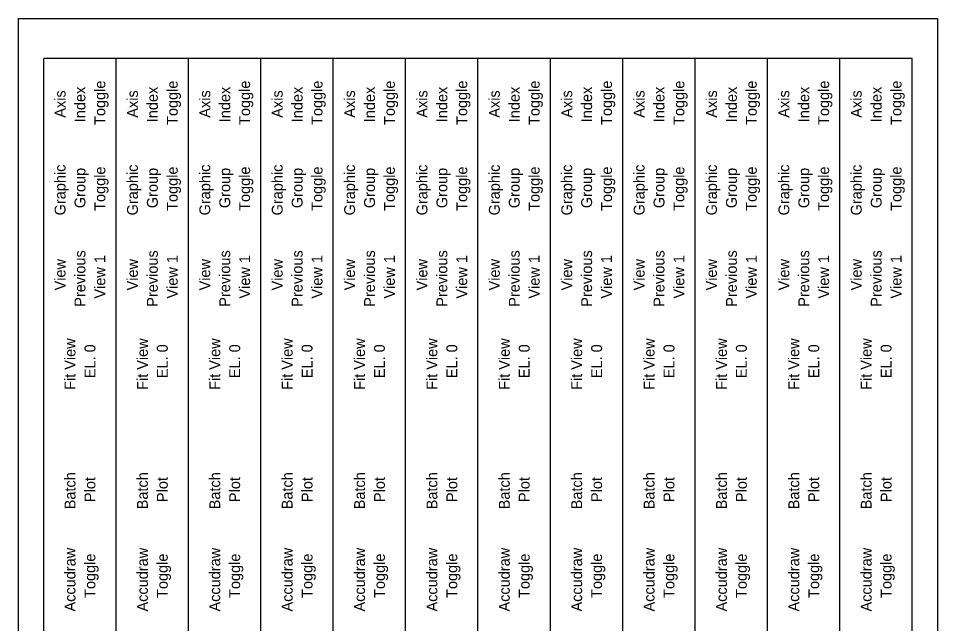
# Model space of a CAD drawing. Extents: x 605371.3 to 605398.1, y 420183.2 to 420214.1.
# Drawn here: x 605390.9472 to 605391.1504, y 420197.4785 to 420197.6124 of the extents above; entities that cross this region are included whole.
import ezdxf

# ---------------------------------------------------------------- set-up
doc = ezdxf.new("R2010")
doc.units = 0
doc.layers.add('Level 60', color=7, linetype='Continuous')
doc.layers.add('Notes', color=7, linetype='Continuous')

msp = doc.modelspace()

# ---------------------------------------------------------------- linework, layer by layer
at = {"layer": 'Level 60'}
msp.add_lwpolyline([(605391.15038, 420197.34467), (605390.94718, 420197.34467), (605390.94718, 420197.61237), (605391.15038, 420197.61237)], close=True, dxfattribs=at)
msp.add_lwpolyline([(605391.15038, 420197.34467), (605390.94718, 420197.34467), (605390.94718, 420197.61237), (605391.15038, 420197.61237)], close=True, dxfattribs=at)
at = {"layer": 'Notes'}
for p, q in [((605390.95278, 420197.35352), (605390.95278, 420197.60352)), ((605390.96878, 420197.60352), (605390.95278, 420197.60352)), ((605390.95278, 420197.35352), (605390.95278, 420197.60352)), ((605390.96878, 420197.60352), (605390.95278, 420197.60352)), ((605390.96878, 420197.35352), (605390.96878, 420197.60352)), ((605390.98478, 420197.60352), (605390.96878, 420197.60352)), ((605390.96878, 420197.35352), (605390.96878, 420197.60352)), ((605390.98478, 420197.60352), (605390.96878, 420197.60352)), ((605390.98478, 420197.35352), (605390.98478, 420197.60352)), ((605391.00078, 420197.60352), (605390.98478, 420197.60352)), ((605390.98478, 420197.35352), (605390.98478, 420197.60352)), ((605391.00078, 420197.60352), (605390.98478, 420197.60352)), ((605391.00078, 420197.35352), (605391.00078, 420197.60352)), ((605391.01678, 420197.60352), (605391.00078, 420197.60352)), ((605391.00078, 420197.35352), (605391.00078, 420197.60352)), ((605391.01678, 420197.60352), (605391.00078, 420197.60352)), ((605391.01678, 420197.35352), (605391.01678, 420197.60352)), ((605391.03278, 420197.60352), (605391.01678, 420197.60352)), ((605391.01678, 420197.35352), (605391.01678, 420197.60352)), ((605391.03278, 420197.60352), (605391.01678, 420197.60352)), ((605391.03278, 420197.35352), (605391.03278, 420197.60352)), ((605391.04878, 420197.60352), (605391.03278, 420197.60352)), ((605391.03278, 420197.35352), (605391.03278, 420197.60352)), ((605391.04878, 420197.60352), (605391.03278, 420197.60352)), ((605391.04878, 420197.35352), (605391.04878, 420197.60352)), ((605391.06478, 420197.60352), (605391.04878, 420197.60352)), ((605391.04878, 420197.35352), (605391.04878, 420197.60352)), ((605391.06478, 420197.60352), (605391.04878, 420197.60352)), ((605391.06478, 420197.35352), (605391.06478, 420197.60352)), ((605391.08078, 420197.60352), (605391.06478, 420197.60352)), ((605391.06478, 420197.35352), (605391.06478, 420197.60352)), ((605391.08078, 420197.60352), (605391.06478, 420197.60352)), ((605391.08078, 420197.35352), (605391.08078, 420197.60352)), ((605391.09678, 420197.60352), (605391.08078, 420197.60352)), ((605391.08078, 420197.35352), (605391.08078, 420197.60352)), ((605391.09678, 420197.60352), (605391.08078, 420197.60352)), ((605391.09678, 420197.35352), (605391.09678, 420197.60352)), ((605391.11278, 420197.60352), (605391.09678, 420197.60352)), ((605391.09678, 420197.35352), (605391.09678, 420197.60352)), ((605391.11278, 420197.60352), (605391.09678, 420197.60352)), ((605391.11278, 420197.35352), (605391.11278, 420197.60352)), ((605391.12878, 420197.60352), (605391.11278, 420197.60352)), ((605391.11278, 420197.35352), (605391.11278, 420197.60352)), ((605391.12878, 420197.60352), (605391.11278, 420197.60352)), ((605391.12878, 420197.35352), (605391.12878, 420197.60352)), ((605391.14478, 420197.60352), (605391.12878, 420197.60352)), ((605391.12878, 420197.35352), (605391.12878, 420197.60352)), ((605391.14478, 420197.60352), (605391.12878, 420197.60352)), ((605391.14478, 420197.35352), (605391.14478, 420197.60352)), ((605391.14478, 420197.35352), (605391.14478, 420197.60352))]:
    msp.add_line(p, q, dxfattribs=at)

# ---------------------------------------------------------------- texts
for s, p in [('Index', (605390.962, 420197.5894)), ('Index', (605390.962, 420197.5894)), ('Toggle', (605390.9664, 420197.5888)), ('Toggle', (605390.9664, 420197.5888)), ('Index', (605390.978, 420197.5894)), ('Index', (605390.978, 420197.5894)), ('Toggle', (605390.9824, 420197.5888)), ('Toggle', (605390.9824, 420197.5888)), ('Index', (605390.994, 420197.5894)), ('Index', (605390.994, 420197.5894)), ('Toggle', (605390.9984, 420197.5888)), ('Toggle', (605390.9984, 420197.5888)), ('Index', (605391.01, 420197.5894)), ('Index', (605391.01, 420197.5894)), ('Toggle', (605391.0144, 420197.5888)), ('Toggle', (605391.0144, 420197.5888)), ('Index', (605391.026, 420197.5894)), ('Index', (605391.026, 420197.5894)), ('Toggle', (605391.0304, 420197.5888)), ('Toggle', (605391.0304, 420197.5888)), ('Index', (605391.042, 420197.5894)), ('Index', (605391.042, 420197.5894)), ('Toggle', (605391.0464, 420197.5888)), ('Toggle', (605391.0464, 420197.5888)), ('Index', (605391.058, 420197.5894)), ('Index', (605391.058, 420197.5894)), ('Toggle', (605391.0624, 420197.5888)), ('Toggle', (605391.0624, 420197.5888)), ('Index', (605391.074, 420197.5894)), ('Index', (605391.074, 420197.5894)), ('Toggle', (605391.0784, 420197.5888)), ('Toggle', (605391.0784, 420197.5888)), ('Index', (605391.09, 420197.5894)), ('Index', (605391.09, 420197.5894)), ('Toggle', (605391.0944, 420197.5888)), ('Toggle', (605391.0944, 420197.5888)), ('Index', (605391.106, 420197.5894)), ('Index', (605391.106, 420197.5894)), ('Toggle', (605391.1104, 420197.5888)), ('Toggle', (605391.1104, 420197.5888)), ('Index', (605391.122, 420197.5894)), ('Index', (605391.122, 420197.5894)), ('Toggle', (605391.1264, 420197.5888)), ('Toggle', (605391.1264, 420197.5888)), ('Index', (605391.138, 420197.5894)), ('Index', (605391.138, 420197.5894)), ('Toggle', (605391.1424, 420197.5888)), ('Toggle', (605391.1424, 420197.5888)), ('Axis', (605390.9576, 420197.5904)), ('Axis', (605390.9576, 420197.5904)), ('Axis', (605390.9736, 420197.5904)), ('Axis', (605390.9736, 420197.5904)), ('Axis', (605390.9896, 420197.5904)), ('Axis', (605390.9896, 420197.5904)), ('Axis', (605391.0056, 420197.5904)), ('Axis', (605391.0056, 420197.5904)), ('Axis', (605391.0216, 420197.5904)), ('Axis', (605391.0216, 420197.5904)), ('Axis', (605391.0376, 420197.5904)), ('Axis', (605391.0376, 420197.5904)), ('Axis', (605391.0536, 420197.5904)), ('Axis', (605391.0536, 420197.5904)), ('Axis', (605391.0696, 420197.5904)), ('Axis', (605391.0696, 420197.5904)), ('Axis', (605391.0856, 420197.5904)), ('Axis', (605391.0856, 420197.5904)), ('Axis', (605391.1016, 420197.5904)), ('Axis', (605391.1016, 420197.5904)), ('Axis', (605391.1176, 420197.5904)), ('Axis', (605391.1176, 420197.5904)), ('Axis', (605391.1336, 420197.5904)), ('Axis', (605391.1336, 420197.5904)), ('Graphic', (605390.9576, 420197.5688)), ('Graphic', (605390.9576, 420197.5688)), ('Group', (605390.962, 420197.5704)), ('Group', (605390.962, 420197.5704)), ('Toggle', (605390.9664, 420197.5698)), ('Toggle', (605390.9664, 420197.5698)), ('Graphic', (605390.9736, 420197.5688)), ('Graphic', (605390.9736, 420197.5688)), ('Group', (605390.978, 420197.5704)), ('Group', (605390.978, 420197.5704)), ('Toggle', (605390.9824, 420197.5698)), ('Toggle', (605390.9824, 420197.5698)), ('Graphic', (605390.9896, 420197.5688)), ('Graphic', (605390.9896, 420197.5688)), ('Group', (605390.994, 420197.5704)), ('Group', (605390.994, 420197.5704)), ('Toggle', (605390.9984, 420197.5698)), ('Toggle', (605390.9984, 420197.5698)), ('Graphic', (605391.0056, 420197.5688)), ('Graphic', (605391.0056, 420197.5688)), ('Group', (605391.01, 420197.5704)), ('Group', (605391.01, 420197.5704)), ('Toggle', (605391.0144, 420197.5698)), ('Toggle', (605391.0144, 420197.5698)), ('Graphic', (605391.0216, 420197.5688)), ('Graphic', (605391.0216, 420197.5688)), ('Group', (605391.026, 420197.5704)), ('Group', (605391.026, 420197.5704)), ('Toggle', (605391.0304, 420197.5698)), ('Toggle', (605391.0304, 420197.5698)), ('Graphic', (605391.0376, 420197.5688)), ('Graphic', (605391.0376, 420197.5688)), ('Group', (605391.042, 420197.5704)), ('Group', (605391.042, 420197.5704)), ('Toggle', (605391.0464, 420197.5698)), ('Toggle', (605391.0464, 420197.5698)), ('Graphic', (605391.0536, 420197.5688)), ('Graphic', (605391.0536, 420197.5688)), ('Group', (605391.058, 420197.5704)), ('Group', (605391.058, 420197.5704)), ('Toggle', (605391.0624, 420197.5698)), ('Toggle', (605391.0624, 420197.5698)), ('Graphic', (605391.0696, 420197.5688)), ('Graphic', (605391.0696, 420197.5688)), ('Group', (605391.074, 420197.5704)), ('Group', (605391.074, 420197.5704)), ('Toggle', (605391.0784, 420197.5698)), ('Toggle', (605391.0784, 420197.5698)), ('Graphic', (605391.0856, 420197.5688)), ('Graphic', (605391.0856, 420197.5688)), ('Group', (605391.09, 420197.5704)), ('Group', (605391.09, 420197.5704)), ('Toggle', (605391.0944, 420197.5698)), ('Toggle', (605391.0944, 420197.5698)), ('Graphic', (605391.1016, 420197.5688)), ('Graphic', (605391.1016, 420197.5688)), ('Group', (605391.106, 420197.5704)), ('Group', (605391.106, 420197.5704)), ('Toggle', (605391.1104, 420197.5698)), ('Toggle', (605391.1104, 420197.5698)), ('Graphic', (605391.1176, 420197.5688)), ('Graphic', (605391.1176, 420197.5688)), ('Group', (605391.122, 420197.5704)), ('Group', (605391.122, 420197.5704)), ('Toggle', (605391.1264, 420197.5698)), ('Toggle', (605391.1264, 420197.5698)), ('Graphic', (605391.1336, 420197.5688)), ('Graphic', (605391.1336, 420197.5688)), ('Group', (605391.138, 420197.5704)), ('Group', (605391.138, 420197.5704)), ('Toggle', (605391.1424, 420197.5698)), ('Toggle', (605391.1424, 420197.5698)), ('Previous', (605390.962, 420197.5486)), ('Previous', (605390.962, 420197.5486)), ('Previous', (605390.978, 420197.5486)), ('Previous', (605390.978, 420197.5486)), ('Previous', (605390.994, 420197.5486)), ('Previous', (605390.994, 420197.5486)), ('Previous', (605391.01, 420197.5486)), ('Previous', (605391.01, 420197.5486)), ('Previous', (605391.026, 420197.5486)), ('Previous', (605391.026, 420197.5486)), ('Previous', (605391.042, 420197.5486)), ('Previous', (605391.042, 420197.5486)), ('Previous', (605391.058, 420197.5486)), ('Previous', (605391.058, 420197.5486)), ('Previous', (605391.074, 420197.5486)), ('Previous', (605391.074, 420197.5486)), ('Previous', (605391.09, 420197.5486)), ('Previous', (605391.09, 420197.5486)), ('Previous', (605391.106, 420197.5486)), ('Previous', (605391.106, 420197.5486)), ('Previous', (605391.122, 420197.5486)), ('Previous', (605391.122, 420197.5486)), ('Previous', (605391.138, 420197.5486)), ('Previous', (605391.138, 420197.5486)), ('View', (605390.9576, 420197.5522)), ('View', (605390.9576, 420197.5522)), ('View 1', (605390.9664, 420197.5504)), ('View 1', (605390.9664, 420197.5504)), ('View', (605390.9736, 420197.5522)), ('View', (605390.9736, 420197.5522)), ('View 1', (605390.9824, 420197.5504)), ('View 1', (605390.9824, 420197.5504)), ('View', (605390.9896, 420197.5522)), ('View', (605390.9896, 420197.5522)), ('View 1', (605390.9984, 420197.5504)), ('View 1', (605390.9984, 420197.5504)), ('View', (605391.0056, 420197.5522)), ('View', (605391.0056, 420197.5522)), ('View 1', (605391.0144, 420197.5504)), ('View 1', (605391.0144, 420197.5504)), ('View', (605391.0216, 420197.5522)), ('View', (605391.0216, 420197.5522)), ('View 1', (605391.0304, 420197.5504)), ('View 1', (605391.0304, 420197.5504)), ('View', (605391.0376, 420197.5522)), ('View', (605391.0376, 420197.5522)), ('View 1', (605391.0464, 420197.5504)), ('View 1', (605391.0464, 420197.5504)), ('View', (605391.0536, 420197.5522)), ('View', (605391.0536, 420197.5522)), ('View 1', (605391.0624, 420197.5504)), ('View 1', (605391.0624, 420197.5504)), ('View', (605391.0696, 420197.5522)), ('View', (605391.0696, 420197.5522)), ('View 1', (605391.0784, 420197.5504)), ('View 1', (605391.0784, 420197.5504)), ('View', (605391.0856, 420197.5522)), ('View', (605391.0856, 420197.5522)), ('View 1', (605391.0944, 420197.5504)), ('View 1', (605391.0944, 420197.5504)), ('View', (605391.1016, 420197.5522)), ('View', (605391.1016, 420197.5522)), ('View 1', (605391.1104, 420197.5504)), ('View 1', (605391.1104, 420197.5504)), ('View', (605391.1176, 420197.5522)), ('View', (605391.1176, 420197.5522)), ('View 1', (605391.1264, 420197.5504)), ('View 1', (605391.1264, 420197.5504)), ('View', (605391.1336, 420197.5522)), ('View', (605391.1336, 420197.5522)), ('View 1', (605391.1424, 420197.5504)), ('View 1', (605391.1424, 420197.5504)), ('Fit View', (605390.9598, 420197.5302)), ('Fit View', (605390.9598, 420197.5302)), ('Fit View', (605390.9758, 420197.5302)), ('Fit View', (605390.9758, 420197.5302)), ('Fit View', (605390.9918, 420197.5302)), ('Fit View', (605390.9918, 420197.5302)), ('Fit View', (605391.0078, 420197.5302)), ('Fit View', (605391.0078, 420197.5302)), ('Fit View', (605391.0238, 420197.5302)), ('Fit View', (605391.0238, 420197.5302)), ('Fit View', (605391.0398, 420197.5302)), ('Fit View', (605391.0398, 420197.5302)), ('Fit View', (605391.0558, 420197.5302)), ('Fit View', (605391.0558, 420197.5302)), ('Fit View', (605391.0718, 420197.5302)), ('Fit View', (605391.0718, 420197.5302)), ('Fit View', (605391.0878, 420197.5302)), ('Fit View', (605391.0878, 420197.5302)), ('Fit View', (605391.1038, 420197.5302)), ('Fit View', (605391.1038, 420197.5302)), ('Fit View', (605391.1198, 420197.5302)), ('Fit View', (605391.1198, 420197.5302)), ('Fit View', (605391.1358, 420197.5302)), ('Fit View', (605391.1358, 420197.5302)), ('EL. 0', (605390.9642, 420197.5328)), ('EL. 0', (605390.9642, 420197.5328)), ('EL. 0', (605390.9802, 420197.5328)), ('EL. 0', (605390.9802, 420197.5328)), ('EL. 0', (605390.9962, 420197.5328)), ('EL. 0', (605390.9962, 420197.5328)), ('EL. 0', (605391.0122, 420197.5328)), ('EL. 0', (605391.0122, 420197.5328)), ('EL. 0', (605391.0282, 420197.5328)), ('EL. 0', (605391.0282, 420197.5328)), ('EL. 0', (605391.0442, 420197.5328)), ('EL. 0', (605391.0442, 420197.5328)), ('EL. 0', (605391.0602, 420197.5328)), ('EL. 0', (605391.0602, 420197.5328)), ('EL. 0', (605391.0762, 420197.5328)), ('EL. 0', (605391.0762, 420197.5328)), ('EL. 0', (605391.0922, 420197.5328)), ('EL. 0', (605391.0922, 420197.5328)), ('EL. 0', (605391.1082, 420197.5328)), ('EL. 0', (605391.1082, 420197.5328)), ('EL. 0', (605391.1242, 420197.5328)), ('EL. 0', (605391.1242, 420197.5328)), ('EL. 0', (605391.1402, 420197.5328)), ('EL. 0', (605391.1402, 420197.5328)), ('Batch', (605390.9598, 420197.5038)), ('Batch', (605390.9598, 420197.5038)), ('Plot', (605390.9642, 420197.5054)), ('Plot', (605390.9642, 420197.5054)), ('Batch', (605390.9758, 420197.5038)), ('Batch', (605390.9758, 420197.5038)), ('Plot', (605390.9802, 420197.5054)), ('Plot', (605390.9802, 420197.5054)), ('Batch', (605390.9918, 420197.5038)), ('Batch', (605390.9918, 420197.5038)), ('Plot', (605390.9962, 420197.5054)), ('Plot', (605390.9962, 420197.5054)), ('Batch', (605391.0078, 420197.5038)), ('Batch', (605391.0078, 420197.5038)), ('Plot', (605391.0122, 420197.5054)), ('Plot', (605391.0122, 420197.5054)), ('Batch', (605391.0238, 420197.5038)), ('Batch', (605391.0238, 420197.5038)), ('Plot', (605391.0282, 420197.5054)), ('Plot', (605391.0282, 420197.5054)), ('Batch', (605391.0398, 420197.5038)), ('Batch', (605391.0398, 420197.5038)), ('Plot', (605391.0442, 420197.5054)), ('Plot', (605391.0442, 420197.5054)), ('Batch', (605391.0558, 420197.5038)), ('Batch', (605391.0558, 420197.5038)), ('Plot', (605391.0602, 420197.5054)), ('Plot', (605391.0602, 420197.5054)), ('Batch', (605391.0718, 420197.5038)), ('Batch', (605391.0718, 420197.5038)), ('Plot', (605391.0762, 420197.5054)), ('Plot', (605391.0762, 420197.5054)), ('Batch', (605391.0878, 420197.5038)), ('Batch', (605391.0878, 420197.5038)), ('Plot', (605391.0922, 420197.5054)), ('Plot', (605391.0922, 420197.5054)), ('Batch', (605391.1038, 420197.5038)), ('Batch', (605391.1038, 420197.5038)), ('Plot', (605391.1082, 420197.5054)), ('Plot', (605391.1082, 420197.5054)), ('Batch', (605391.1198, 420197.5038)), ('Batch', (605391.1198, 420197.5038)), ('Plot', (605391.1242, 420197.5054)), ('Plot', (605391.1242, 420197.5054)), ('Batch', (605391.1358, 420197.5038)), ('Batch', (605391.1358, 420197.5038)), ('Plot', (605391.1402, 420197.5054)), ('Plot', (605391.1402, 420197.5054)), ('Accudraw', (605390.9598, 420197.4812)), ('Accudraw', (605390.9598, 420197.4812)), ('Toggle', (605390.9642, 420197.4842)), ('Toggle', (605390.9642, 420197.4842)), ('Accudraw', (605390.9758, 420197.4812)), ('Accudraw', (605390.9758, 420197.4812)), ('Toggle', (605390.9802, 420197.4842)), ('Toggle', (605390.9802, 420197.4842)), ('Accudraw', (605390.9918, 420197.4812)), ('Accudraw', (605390.9918, 420197.4812)), ('Toggle', (605390.9962, 420197.4842)), ('Toggle', (605390.9962, 420197.4842)), ('Accudraw', (605391.0078, 420197.4812)), ('Accudraw', (605391.0078, 420197.4812)), ('Toggle', (605391.0122, 420197.4842)), ('Toggle', (605391.0122, 420197.4842)), ('Accudraw', (605391.0238, 420197.4812)), ('Accudraw', (605391.0238, 420197.4812)), ('Toggle', (605391.0282, 420197.4842)), ('Toggle', (605391.0282, 420197.4842)), ('Accudraw', (605391.0398, 420197.4812)), ('Accudraw', (605391.0398, 420197.4812)), ('Toggle', (605391.0442, 420197.4842)), ('Toggle', (605391.0442, 420197.4842)), ('Accudraw', (605391.0558, 420197.4812)), ('Accudraw', (605391.0558, 420197.4812)), ('Toggle', (605391.0602, 420197.4842)), ('Toggle', (605391.0602, 420197.4842)), ('Accudraw', (605391.0718, 420197.4812)), ('Accudraw', (605391.0718, 420197.4812)), ('Toggle', (605391.0762, 420197.4842)), ('Toggle', (605391.0762, 420197.4842)), ('Accudraw', (605391.0878, 420197.4812)), ('Accudraw', (605391.0878, 420197.4812)), ('Toggle', (605391.0922, 420197.4842)), ('Toggle', (605391.0922, 420197.4842)), ('Accudraw', (605391.1038, 420197.4812)), ('Accudraw', (605391.1038, 420197.4812)), ('Toggle', (605391.1082, 420197.4842)), ('Toggle', (605391.1082, 420197.4842)), ('Accudraw', (605391.1198, 420197.4812)), ('Accudraw', (605391.1198, 420197.4812)), ('Toggle', (605391.1242, 420197.4842)), ('Toggle', (605391.1242, 420197.4842)), ('Accudraw', (605391.1358, 420197.4812)), ('Accudraw', (605391.1358, 420197.4812)), ('Toggle', (605391.1402, 420197.4842)), ('Toggle', (605391.1402, 420197.4842))]:
    msp.add_text(s, height=0.0024, rotation=90, dxfattribs=at).set_placement(p)

doc.saveas('drawing.dxf')
